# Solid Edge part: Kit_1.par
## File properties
Sűrűség: 0,000 kg/m^3
Pontosság: 0,990
Author: ahadarics
Last saved by: psaghy
Revision: 78
Username: ahadarics
Dokumentum tartalom típus: 0
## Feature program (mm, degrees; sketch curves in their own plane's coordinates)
base feature "unnamed BaseFeature 1"
sketch for "Furat_1" plane through (0, 0, 37) normal (0, 0, 1) x-axis (0, -1, 0)
  hole centre (-19, 19) bore radius 2.4585
hole "Furat_1" nominal diameter 6 finite  VBottomAngle = 118 deg
sketch for "unnamed Hole 1" plane through (0, 0, 37) normal (0, 0, 1) x-axis (0, -1, 0)
  hole centre (-19, -19) bore radius 2.4585
hole "unnamed Hole 1" finite
sketch for "unnamed Hole 2" plane through (0, 0, 37) normal (0, 0, 1) x-axis (0, -1, 0)
  hole centre (19, -19) bore radius 2.4585
hole "unnamed Hole 2" finite
sketch for "unnamed Hole 3" plane through (0, 0, 37) normal (0, 0, 1) x-axis (0, -1, 0)
  hole centre (19, 19) bore radius 2.4585
hole "unnamed Hole 3" finite
pattern "unnamed Pattern 1" of "Furat_1", "unnamed Hole 1", "unnamed Hole 2", "unnamed Hole 3"
sketch for "Furat_5" plane through (27.25, 0, 19.2488) normal (1, 0, 0) x-axis (0, 0, 1)
hole "Furat_5" diameter 13.157 finite  ThreadDepth = 12 mm
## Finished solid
Body 1: solid body, 333 faces, 787 edges, 500 vertices, 2 internal voids.
  Faces by surface: plane 137, cylinder 90, torus 32, spline 31, cone 28, sphere 9, swept 6
  Edges by curve: line 342, circle 234, curve on surface 184, spline 27
Bounding box of the edges (mm; curved faces can reach further): 54.500 x 54.500 x 35.000, from (-27.25, -27.25, 6) to (27.25, 27.25, 41).
Cylindrical faces by radius (mm): R0.2344 x1, R0.4113 x1, R0.4771 x1, R0.5 x7, R0.5094 x1, R0.5226 x1, R0.5534 x1, R0.6836 x1, R0.7041 x1, R0.7049 x1, R0.7519 x1, R0.7795 x1, R0.7904 x1, R0.8051 x1, R0.824 x1, R0.8903 x1, R0.9421 x1, R0.9541 x2, R1 x12, R1.0216 x1, R1.0284 x1, R1.25 x1, R1.2857 x1, R2.4585 x8, R3 x4, R3.1 x4, R3.5 x1, R4.95 x1, R5 x7, R5.15 x4, R5.72 x1, R5.7225 x1, R7.5 x1, R8.25 x4, R8.7 x1, R10 x2, R17.5 x1, R23 x3, R27.5 x6
Conical faces (half-angle, radius in mm at the cone's reference point): 29.0546 deg R23.75 x4, 30 deg R5.1443 x1, 45 deg R2.75 x1, 45 deg R2.825 x1, 45 deg R3.25 x8, 45 deg R4.85 x8, 45 deg R6.72 x1, 59 deg R2.4585 x4
Toroidal faces (ring radius, tube radius in mm): R0.9686 r0.5 x1, R1.4708 r0.5006 x3, R3.3 r0.3 x4, R4.7 r0.3 x1, R4.95 r0.2 x4, R5.65 r0.5 x4, R8.75 r0.5 x2, R9.5 r0.5 x1, R17 r0.5 x1, R18 r0.5 x1, R22 r1 x3, R26.5 r1 x6, R27.7942 r0.5 x1
Spherical faces by radius (mm): R0.5 x3, R1 x6
Planar faces by outward normal: +x 25, +y 10, +z 27, -x 5, -y 9, -z 19, oblique 42
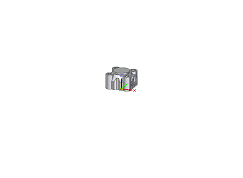
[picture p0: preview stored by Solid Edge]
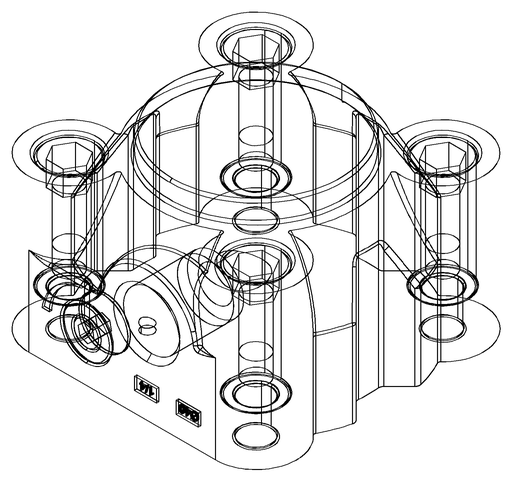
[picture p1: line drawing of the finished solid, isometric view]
